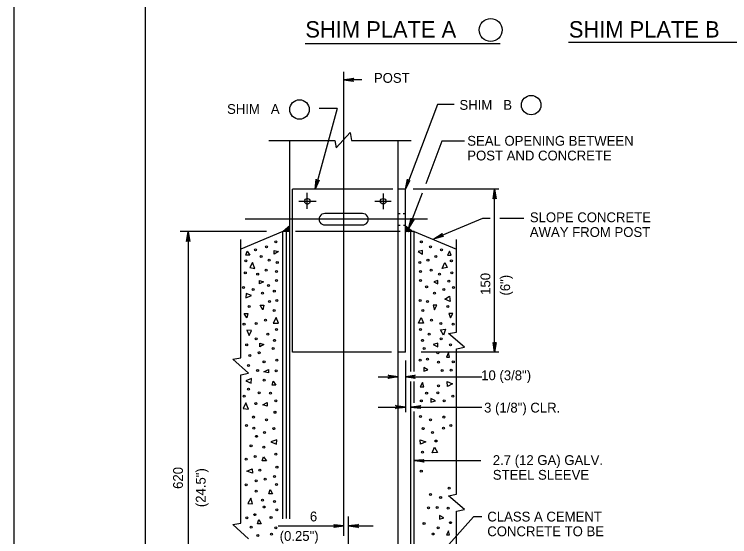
# Model space of a CAD drawing. Extents: x 649454 to 651200, y 295188 to 295782.
# Drawn here: x 649454.3 to 649672.9, y 295328.7 to 295488.4 of the extents above; entities that cross this region are included whole.
import ezdxf

# ---------------------------------------------------------------- set-up
doc = ezdxf.new("R2010")
doc.units = 0
for name, color, linetype in [('1', 7, 'Continuous'), ('2', 7, 'Continuous'), ('3', 7, 'Continuous'), ('PLT-BNDY', 7, 'Continuous')]:
    doc.layers.add(name, color=color, linetype=linetype)

msp = doc.modelspace()

# ---------------------------------------------------------------- linework, layer by layer
at = {"layer": '1'}
msp.add_line((649494.31, 295766.63), (649494.31, 295202.63), dxfattribs=at)
at = {"layer": '2'}
for p, q in [((649543.17, 295479.45), (649602.74, 295479.45)), ((649623.66, 295479.8), (649683.23, 295479.8)), ((649554.94, 295328.93), (649554.94, 295470.8)), ((649552.69, 295447.55), (649556.94, 295452.18)), ((649556.94, 295452.18), (649557.31, 295449.8)), ((649532.06, 295449.8), (649552.19, 295449.8)), ((649538.44, 295334.16), (649538.44, 295449.8)), ((649552.19, 295449.8), (649552.69, 295447.55)), ((649557.31, 295449.8), (649575.56, 295449.8)), ((649571.56, 295273.3), (649571.56, 295449.8)), ((649569.94, 295434.93), (649539.31, 295434.93)), ((649539.31, 295385.05), (649539.31, 295434.93)), ((649573.81, 295434.93), (649571.56, 295434.93)), ((649573.81, 295385.05), (649573.81, 295434.93)), ((649543.81, 295428.93), (649543.81, 295433.8)), ((649567.06, 295428.8), (649567.06, 295433.55)), ((649546.56, 295431.18), (649541.19, 295431.18)), ((649569.44, 295431.18), (649564.44, 295431.18)), ((649580.56, 295425.68), (649524.81, 295425.68)), ((649560.69, 295427.43), (649549.19, 295427.43)), ((649571.56, 295427.43), (649572.19, 295427.43)), ((649573.06, 295427.43), (649573.81, 295427.43)), ((649538.44, 295423.68), (649536.44, 295421.93)), ((649560.69, 295423.93), (649549.19, 295423.93)), ((649571.56, 295423.93), (649572.19, 295423.93)), ((649573.19, 295423.93), (649573.81, 295423.93)), ((649573.81, 295423.68), (649576.06, 295421.93)), ((649536.31, 295421.93), (649523.56, 295416.55)), ((649538.44, 295421.93), (649536.31, 295421.93)), ((649536.31, 295334.16), (649536.31, 295421.93)), ((649538.44, 295423.43), (649536.69, 295421.93)), ((649538.44, 295423.05), (649536.94, 295421.93)), ((649538.44, 295422.8), (649537.31, 295422.05)), ((649537.44, 295334.25), (649537.44, 295421.93)), ((649538.44, 295422.55), (649537.56, 295421.93)), ((649538.44, 295422.3), (649537.94, 295422.05)), ((649538.44, 295422.05), (649538.19, 295421.93)), ((649572.19, 295421.93), (649540.19, 295421.93)), ((649573.81, 295423.43), (649575.69, 295421.93)), ((649573.81, 295423.05), (649575.31, 295421.93)), ((649573.81, 295422.8), (649574.94, 295421.93)), ((649573.81, 295422.55), (649574.69, 295421.93)), ((649573.81, 295422.3), (649574.31, 295421.93)), ((649573.81, 295422.05), (649573.94, 295421.93)), ((649576.44, 295421.93), (649573.81, 295421.93)), ((649575.44, 295379.18), (649575.44, 295421.93)), ((649576.44, 295421.93), (649589.44, 295416.55)), ((649576.44, 295379.18), (649576.44, 295421.93)), ((649523.56, 295383.3), (649523.56, 295419.55)), ((649589.44, 295391.18), (649589.44, 295419.55)), ((649586.94, 295390.8), (649589.44, 295391.18)), ((649591.81, 295386.55), (649586.94, 295390.8)), ((649589.44, 295386.05), (649591.81, 295386.55)), ((649569.56, 295385.05), (649539.31, 295385.05)), ((649573.81, 295385.05), (649571.56, 295385.05)), ((649589.44, 295341.68), (649589.44, 295386.05)), ((649521.06, 295382.93), (649523.56, 295383.3)), ((649525.81, 295378.68), (649521.06, 295382.93)), ((649523.56, 295378.18), (649525.81, 295378.68)), ((649523.56, 295332.8), (649523.56, 295378.18)), ((649575.44, 295254.8), (649575.44, 295376.05)), ((649576.44, 295369.55), (649576.44, 295376.05)), ((649576.44, 295254.8), (649576.44, 295366.93)), ((649586.94, 295341.18), (649589.44, 295341.68)), ((649591.81, 295336.93), (649586.94, 295341.18)), ((649589.44, 295336.43), (649591.81, 295336.93)), ((649589.44, 295297.68), (649589.44, 295336.43)), ((649556.44, 295305.3), (649556.44, 295334.8)), ((649521.06, 295332.43), (649523.56, 295332.8)), ((649525.81, 295328.05), (649521.06, 295332.43))]:
    msp.add_line(p, q, dxfattribs=at)
for points in [[(649526.31, 295414.68), (649525.06, 295414.68), (649525.44, 295415.93)], [(649533.69, 295415.05), (649533.69, 295416.18), (649535.06, 295415.8)], [(649579.06, 295415.05), (649579.06, 295416.18), (649577.69, 295415.8)], [(649586.69, 295414.68), (649587.81, 295414.68), (649587.31, 295415.93)], [(649526.31, 295410.93), (649527.81, 295410.68), (649527.06, 295412.43)], [(649586.56, 295410.93), (649585.06, 295410.68), (649585.81, 295412.43)], [(649529.19, 295405.93), (649529.19, 295406.93), (649530.44, 295406.55)], [(649583.69, 295405.93), (649583.69, 295406.93), (649582.44, 295406.55)], [(649525.19, 295403.05), (649525.06, 295401.68), (649526.81, 295402.43)], [(649587.31, 295402.18), (649587.44, 295400.55), (649585.81, 295401.3)], [(649529.44, 295399.43), (649530.56, 295399.43), (649530.19, 295398.05)], [(649583.44, 295399.43), (649582.31, 295399.43), (649582.69, 295398.05)], [(649524.56, 295396.93), (649525.69, 295396.93), (649525.31, 295395.55)], [(649533.44, 295393.93), (649535.06, 295393.93), (649534.31, 295395.68)], [(649579.31, 295393.93), (649577.81, 295393.93), (649578.56, 295395.68)], [(649588.31, 295396.93), (649587.06, 295396.93), (649587.56, 295395.55)], [(649526.81, 295391.68), (649525.31, 295391.8), (649526.06, 295390.18)], [(649584.56, 295391.93), (649586.06, 295392.05), (649585.44, 295390.3)], [(649529.31, 295386.68), (649529.31, 295387.8), (649530.56, 295387.43)], [(649583.69, 295386.68), (649583.69, 295387.8), (649582.31, 295387.43)], [(649586.31, 295383.55), (649587.31, 295383.55), (649586.94, 295384.93)], [(649531.94, 295379.8), (649531.94, 295378.8), (649530.56, 295379.05)], [(649579.44, 295380.43), (649579.44, 295379.3), (649580.69, 295379.68)], [(649526.69, 295375.55), (649526.81, 295377.05), (649525.06, 295376.3)], [(649534.19, 295374.93), (649533.06, 295374.93), (649533.44, 295376.18)], [(649578.31, 295374.43), (649579.44, 295374.43), (649579.06, 295375.8)], [(649586.69, 295374.55), (649586.56, 295376.05), (649588.19, 295375.43)], [(649524.19, 295367.8), (649525.81, 295367.68), (649525.06, 295369.55)], [(649531.56, 295369.68), (649531.56, 295368.55), (649530.19, 295368.93)], [(649581.56, 295370.93), (649581.56, 295369.8), (649582.94, 295370.18)], [(649534.44, 295356.93), (649534.56, 295358.3), (649532.69, 295357.68)], [(649578.44, 295356.93), (649578.31, 295358.3), (649580.06, 295357.68)], [(649583.56, 295354.43), (649581.94, 295354.3), (649582.69, 295356.05)], [(649531.31, 295351.8), (649530.06, 295351.8), (649530.44, 295353.05)], [(649526.94, 295349.43), (649527.06, 295348.05), (649525.31, 295348.68)], [(649533.19, 295341.8), (649532.06, 295341.8), (649532.44, 295343.05)], [(649525.69, 295338.8), (649527.06, 295338.68), (649526.56, 295340.43)], [(649529.69, 295332.55), (649528.56, 295332.55), (649529.06, 295333.93)], [(649584.19, 295335.18), (649584.19, 295334.05), (649585.56, 295334.43)], [(649586.31, 295329.18), (649587.31, 295329.18), (649586.94, 295330.43)]]:
    msp.add_lwpolyline(points, close=True, dxfattribs=at)
for centre, radius in [((649543.85, 295431.19), 0.856), ((649567.01, 295431.19), 0.856), ((649534.19, 295418.83), 0.301), ((649578.66, 295418.83), 0.301), ((649531.36, 295417.26), 0.301), ((649581.49, 295417.26), 0.301), ((649527.99, 295416.32), 0.301), ((649584.86, 295416.32), 0.301), ((649525.03, 295412.95), 0.301), ((649529.74, 295414.3), 0.301), ((649532.17, 295413.22), 0.301), ((649534.66, 295412.45), 0.301), ((649578.19, 295412.45), 0.301), ((649580.69, 295413.22), 0.301), ((649583.11, 295414.3), 0.301), ((649587.83, 295412.95), 0.301), ((649531.22, 295410.12), 0.301), ((649581.63, 295410.12), 0.301), ((649524.89, 295409.31), 0.301), ((649528.66, 295408.91), 0.301), ((649534.43, 295409.73), 0.301), ((649578.43, 295409.73), 0.301), ((649584.19, 295408.91), 0.301), ((649587.96, 295409.31), 0.301), ((649534.43, 295407.01), 0.301), ((649578.43, 295407.01), 0.301), ((649587.02, 295406.75), 0.301), ((649524.35, 295404.86), 0.301), ((649527.32, 295404.19), 0.301), ((649531.98, 295405.45), 0.301), ((649533.75, 295403.7), 0.301), ((649580.28, 295405), 0.301), ((649585.54, 295404.19), 0.301), ((649588.5, 295404.86), 0.301), ((649530.15, 295403.11), 0.301), ((649582.71, 295403.11), 0.301), ((649532.3, 295400.55), 0.301), ((649534.55, 295400.86), 0.301), ((649578.31, 295400.86), 0.301), ((649580.55, 295400.55), 0.301), ((649526.1, 295399.06), 0.301), ((649533.72, 295397.78), 0.301), ((649579.13, 295397.78), 0.301), ((649586.75, 295399.06), 0.301), ((649531.09, 295394.89), 0.301), ((649581.76, 295394.89), 0.301), ((649524.49, 295393.67), 0.301), ((649528.22, 295393.84), 0.301), ((649584.63, 295393.84), 0.301), ((649588.37, 295393.67), 0.301), ((649531.76, 295390.57), 0.301), ((649534.43, 295391.99), 0.301), ((649578.43, 295391.99), 0.301), ((649581.09, 295390.57), 0.301), ((649528.18, 295389.18), 0.301), ((649533.84, 295388.68), 0.301), ((649579.01, 295388.68), 0.301), ((649584.68, 295389.18), 0.301), ((649525.3, 295387.33), 0.301), ((649533.37, 295386.2), 0.301), ((649579.49, 295386.2), 0.301), ((649587.56, 295387.33), 0.301), ((649526.27, 295384.07), 0.301), ((649529.13, 295384.91), 0.301), ((649583.72, 295384.91), 0.301), ((649530.6, 295382.1), 0.301), ((649534.55, 295382.65), 0.301), ((649578.31, 295382.65), 0.301), ((649580.55, 295382.89), 0.301), ((649583.91, 295381.98), 0.301), ((649588.43, 295382.08), 0.301), ((649525.84, 295381.01), 0.301), ((649528.65, 295379.5), 0.301), ((649585.03, 295379.5), 0.301), ((649587.76, 295379.53), 0.301), ((649534.31, 295379.34), 0.301), ((649530.68, 295376.55), 0.301), ((649525.83, 295373.72), 0.301), ((649583.94, 295374.78), 0.301), ((649524.55, 295371.63), 0.301), ((649529.11, 295372.64), 0.301), ((649532.57, 295372.5), 0.301), ((649580.28, 295372.5), 0.301), ((649583.74, 295372.64), 0.301), ((649588.3, 295371.63), 0.301), ((649528.14, 295369.33), 0.301), ((649534.19, 295370.23), 0.301), ((649578.66, 295370.23), 0.301), ((649585.66, 295370.16), 0.301), ((649533.95, 295366.68), 0.301), ((649527.35, 295365.24), 0.301), ((649531.36, 295364.41), 0.301), ((649578.43, 295365.38), 0.301), ((649581.49, 295364.41), 0.301), ((649585.51, 295365.24), 0.301), ((649525.22, 295362.63), 0.301), ((649587.63, 295362.63), 0.301), ((649527.47, 295361.81), 0.301), ((649530.77, 295360.51), 0.301), ((649533.61, 295361.69), 0.301), ((649579.24, 295361.69), 0.301), ((649582.08, 295360.51), 0.301), ((649585.39, 295361.81), 0.301), ((649528.34, 295359.34), 0.301), ((649583.14, 295357.91), 0.301), ((649526.63, 295356.47), 0.301), ((649530.54, 295356.01), 0.301), ((649534.2, 295353.88), 0.301), ((649579.01, 295354.48), 0.301), ((649525.18, 295352.32), 0.301), ((649527.93, 295353.14), 0.301), ((649529.3, 295349.01), 0.301), ((649534.56, 295349.87), 0.301), ((649533.84, 295347.09), 0.301), ((649578.65, 295348.68), 0.301), ((649528.2, 295345.71), 0.301), ((649530.95, 295346.26), 0.301), ((649534.39, 295344.61), 0.301), ((649525.18, 295344.47), 0.301), ((649528.2, 295342.54), 0.301), ((649587.16, 295343.48), 0.301), ((649581.49, 295341.55), 0.301), ((649584.56, 295340.64), 0.301), ((649530.13, 295339.79), 0.301), ((649533.84, 295339.38), 0.301), ((649530.68, 295337.73), 0.301), ((649534.53, 295336.9), 0.301), ((649580.87, 295337.5), 0.301), ((649583.47, 295337.54), 0.301), ((649586.82, 295337.36), 0.301), ((649525.31, 295334.42), 0.301), ((649527.79, 295335.39), 0.301), ((649532.74, 295334.56), 0.301), ((649526.69, 295331.53), 0.301), ((649579.48, 295332.72), 0.301), ((649587.56, 295332.94), 0.301), ((649532.88, 295329.47), 0.301), ((649534.25, 295331.39), 0.301), ((649582.25, 295329.48), 0.301), ((649583.84, 295331.34), 0.301), ((649528.75, 295329.05), 0.301)]:
    msp.add_circle(centre, radius, dxfattribs=at)
for centre, start, end in [((649549.16, 295425.7), 89.2551, 271.9772), ((649560.7, 295425.7), 268.0228, 90.7449)]:
    msp.add_arc(centre, 1.74, start, end, dxfattribs=at)
at = {"layer": '3'}
for p, q in [((649560.44, 295468.3), (649554.94, 295468.3)), ((649583.56, 295460.8), (649573.81, 295434.93)), ((649588.69, 295460.8), (649583.56, 295460.8)), ((649552.94, 295459.55), (649546.19, 295434.93)), ((649552.94, 295459.55), (649547.44, 295459.55)), ((649584.94, 295449.55), (649580.06, 295436.55)), ((649591.81, 295449.55), (649584.94, 295449.55)), ((649602.31, 295434.93), (649576.19, 295434.93)), ((649601.06, 295385.05), (649601.06, 295434.93)), ((649578.94, 295433.68), (649574.81, 295423.05)), ((649597.31, 295425.93), (649582.44, 295419.68)), ((649599.69, 295425.93), (649597.31, 295425.93)), ((649609.94, 295425.93), (649602.69, 295425.93)), ((649531.31, 295421.93), (649504.94, 295421.93)), ((649507.44, 295421.93), (649507.44, 295272.05)), ((649602.31, 295385.05), (649578.56, 295385.05)), ((649573.81, 295382.55), (649573.81, 295366.68)), ((649565.44, 295377.55), (649571.56, 295377.55)), ((649573.81, 295377.55), (649597.12, 295377.55)), ((649565.44, 295368.3), (649573.81, 295368.3)), ((649575.44, 295368.3), (649597.12, 295368.3)), ((649576.44, 295351.93), (649596.86, 295351.93)), ((649554.94, 295328.93), (649554.94, 295334.8)), ((649556.44, 295328.93), (649556.44, 295334.8)), ((649594.56, 295334.68), (649582.94, 295321.68)), ((649597.19, 295334.68), (649594.56, 295334.68)), ((649534.97, 295331.93), (649554.94, 295331.93)), ((649556.44, 295331.93), (649563.94, 295331.93))]:
    msp.add_line(p, q, dxfattribs=at)
for points in [[(649557.81, 295467.93), (649557.69, 295468.18), (649554.94, 295468.3), (649557.81, 295467.93), (649557.94, 295467.8), (649554.94, 295468.3), (649557.69, 295468.43), (649557.81, 295468.68), (649554.94, 295468.3), (649557.94, 295468.8), (649557.81, 295468.68)], [(649547.31, 295437.55), (649547.06, 295437.55), (649546.19, 295434.93), (649547.31, 295437.55), (649547.44, 295437.68), (649546.19, 295434.93), (649546.81, 295437.55), (649546.56, 295437.8), (649546.19, 295434.93), (649546.56, 295437.93), (649546.56, 295437.8)], [(649575.06, 295437.43), (649574.81, 295437.43), (649573.81, 295434.93), (649575.06, 295437.43), (649575.19, 295437.55), (649573.81, 295434.93), (649574.69, 295437.55), (649574.44, 295437.68), (649573.81, 295434.93), (649574.44, 295437.93), (649574.44, 295437.68)], [(649600.69, 295432.05), (649600.81, 295432.18), (649601.06, 295434.93), (649600.69, 295432.05), (649600.56, 295431.93), (649601.06, 295434.93), (649601.19, 295432.18), (649601.44, 295432.05), (649601.06, 295434.93), (649601.56, 295431.93), (649601.44, 295432.05)], [(649576.31, 295425.55), (649576.06, 295425.55), (649574.81, 295423.05), (649576.31, 295425.55), (649576.44, 295425.68), (649574.81, 295423.05), (649575.69, 295425.68), (649575.56, 295425.8), (649574.81, 295423.05), (649575.56, 295426.05), (649575.56, 295425.8)], [(649507.07, 295419.05), (649507.19, 295419.18), (649507.44, 295421.93), (649507.07, 295419.05), (649506.94, 295418.93), (649507.44, 295421.93), (649507.57, 295419.18), (649507.82, 295419.18), (649507.44, 295421.93), (649507.94, 295418.93), (649507.82, 295419.18)], [(649585.31, 295420.55), (649585.06, 295420.68), (649582.44, 295419.68), (649585.31, 295420.55), (649585.44, 295420.43), (649582.44, 295419.68), (649584.94, 295420.93), (649584.94, 295421.05), (649582.44, 295419.68), (649585.06, 295421.3), (649584.94, 295421.05)], [(649601.44, 295387.93), (649601.19, 295387.93), (649601.06, 295385.05), (649601.44, 295387.93), (649601.56, 295388.05), (649601.06, 295385.05), (649600.94, 295387.93), (649600.69, 295387.93), (649601.06, 295385.05), (649600.56, 295388.05), (649600.69, 295387.93)], [(649568.69, 295377.93), (649568.69, 295377.8), (649571.56, 295377.55), (649568.69, 295377.93), (649568.56, 295378.05), (649571.56, 295377.55), (649568.69, 295377.43), (649568.69, 295377.3), (649571.56, 295377.55), (649568.56, 295377.05), (649568.69, 295377.3)], [(649576.56, 295377.18), (649576.44, 295377.43), (649573.81, 295377.55), (649576.56, 295377.18), (649576.81, 295377.05), (649573.81, 295377.55), (649576.44, 295377.8), (649576.56, 295377.93), (649573.81, 295377.55), (649576.81, 295378.05), (649576.56, 295377.93)], [(649570.94, 295368.68), (649571.06, 295368.43), (649573.81, 295368.3), (649570.94, 295368.68), (649570.81, 295368.8), (649573.81, 295368.3), (649571.06, 295368.05), (649570.94, 295367.93), (649573.81, 295368.3), (649570.81, 295367.8), (649570.94, 295367.93)], [(649578.31, 295367.93), (649578.19, 295368.05), (649575.44, 295368.3), (649578.31, 295367.93), (649578.44, 295367.8), (649575.44, 295368.3), (649578.19, 295368.43), (649578.31, 295368.55), (649575.44, 295368.3), (649578.44, 295368.8), (649578.31, 295368.55)], [(649579.31, 295351.68), (649579.19, 295351.8), (649576.44, 295351.93), (649579.31, 295351.68), (649579.44, 295351.43), (649576.44, 295351.93), (649579.19, 295352.05), (649579.31, 295352.18), (649576.44, 295351.93), (649579.44, 295352.3), (649579.31, 295352.18)], [(649552.06, 295332.3), (649552.19, 295332.05), (649554.94, 295331.93), (649552.06, 295332.3), (649551.94, 295332.43), (649554.94, 295331.93), (649552.19, 295331.8), (649552.06, 295331.55), (649554.94, 295331.93), (649551.94, 295331.43), (649552.06, 295331.55)], [(649559.31, 295331.55), (649559.19, 295331.8), (649556.44, 295331.93), (649559.31, 295331.55), (649559.44, 295331.43), (649556.44, 295331.93), (649559.19, 295332.05), (649559.31, 295332.3), (649556.44, 295331.93), (649559.44, 295332.43), (649559.31, 295332.3)]]:
    msp.add_lwpolyline(points, dxfattribs=at)
for centre, radius in [((649599.84, 295483.57), 3.5), ((649612.21, 295460.6), 2.98), ((649541.44, 295459.26), 2.98)]:
    msp.add_circle(centre, radius, dxfattribs=at)
at = {"layer": 'PLT-BNDY'}
msp.add_lwpolyline([(649454.31, 295781.63), (650295.31, 295781.63), (650295.31, 295187.63), (649454.31, 295187.63)], close=True, dxfattribs=at)

# ---------------------------------------------------------------- texts
at = {"layer": '2'}
for s, height, p in [('SHIM PLATE A', 5, (649543.23, 295481.26)), ('SHIM PLATE B', 5, (649623.72, 295481.26)), ('  POST', 3, (649561.94, 295467.41)), ('SHIM   A ', 3, (649519.31, 295457.91)), ('SHIM   B ', 3, (649590.31, 295459.16)), ('SEAL OPENING BETWEEN', 3, (649592.69, 295448.18)), ('POST AND CONCRETE', 3, (649592.69, 295443.68)), ('SLOPE CONCRETE', 3, (649611.81, 295424.8)), ('AWAY FROM POST', 3, (649611.81, 295420.3)), ('CLASS A CEMENT', 3, (649598.81, 295333.3)), ('CONCRETE TO BE', 3, (649598.81, 295328.8))]:
    msp.add_text(s, height=height, dxfattribs=at).set_placement(p)
at = {"layer": '3'}
for s, p in [('150 ', (649599.74, 295402.6)), ('(6")', (649605.77, 295402.38)), ('620 ', (649505.82, 295343.27)), ('(24.5")', (649512.77, 295337.69))]:
    msp.add_text(s, height=3, rotation=90, dxfattribs=at).set_placement(p)
for s, p in [(' 10 (3/8")', (649595.83, 295376.5)), (' 3 (1/8") CLR.', (649596.72, 295366.61)), ('2.7 (12 GA) GALV.', (649600.49, 295350.57)), ('STEEL SLEEVE', (649600.49, 295346.07)), ('6', (649544.61, 295333.33)), ('(0.25")', (649535.38, 295327.38))]:
    msp.add_text(s, height=3, dxfattribs=at).set_placement(p)

doc.saveas('drawing.dxf')
